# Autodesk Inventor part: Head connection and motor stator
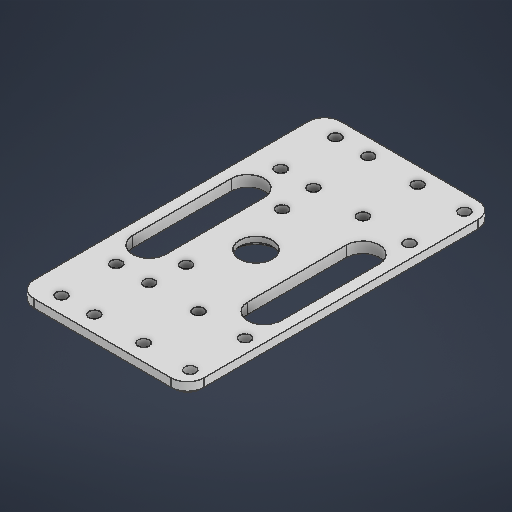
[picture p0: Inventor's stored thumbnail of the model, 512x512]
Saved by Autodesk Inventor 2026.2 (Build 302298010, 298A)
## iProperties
Created: 2026-05
Part Number: Head connection and motor stator
Material: 일반
Document SubType Name: Modeling
Designer: work
Density: 1 g/cm^3
Appearance: 기본값
Author: work
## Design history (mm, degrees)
sketch "스케치1"
  geometry: L1 (-9, 10)-(-26, 10); L2 (-26, 10)-(-26, -10); L3 (-26, -10)-(-9, -10); L4 (-9, -10)-(-9, 10); L5 (-9, 0)-(9, 0); L6 (21, 10)-(9, 10); L7 (9, 10)-(9, -10); L8 (9, -10)-(21, -10); L9 (21, -10)-(21, 10); L10 (-9, -90)-(-9, -70); L11 (-9, -70)-(-26, -70); L12 (-26, -70)-(-26, -90); L13 (-26, -90)-(-9, -90); L14 (-9, -80)-(9, -80); L15 (9, -70)-(9, -90); L16 (9, -90)-(21, -90); L17 (21, -70)-(9, -70); L18 (21, -90)-(21, -70); L19 (0, 0)-(0, -80); L20 (0, -40)-(8, -40); L21 (8, -22.5)-(8, -57.5); L22 (8, -22.5)-(43, -22.5); L23 (-31, 16)-(31, 16); L24 (31, 16)-(31, -96); L25 (31, -96)-(-31, -96); L26 (-31, -96)-(-31, 16); L27 (-31, 16)-(31, -96); L28 (31, 16)-(-31, -96); L29 (-27, -16)-(-15, -16); L30 (-15, -16)-(-15, -64); L31 (-15, -64)-(-27, -64); L32 (-27, -64)-(-27, -16); L33 (-27, -16)-(-15, -64); L34 (-15, -16)-(-27, -64); L35 (-31, -40)-(31, -40); L36 (31, -40)-(-31, -40); L37 (15, -16)-(15, -64); L38 (27, -64)-(27, -16); L39 (27, -16)-(15, -64); L40 (15, -16)-(27, -64); L41 (31, 16)-(-31, -96); L42 (-31, 16)-(31, -96); L43 (27, -16)-(15, -16); L44 (15, -64)-(27, -64); C1 r 2 at (21, 10); C2 r 2 at (9, 10); C3 r 2 at (9, -10); C4 r 2 at (21, -10); C5 r 2 at (-9, 10); C6 r 2 at (-9, -10); C7 r 2 at (-26, -10); C8 r 2 at (-26, 10); C9 r 2 at (-9, -70); C10 r 2 at (-9, -90); C11 r 2 at (-26, -70); C12 r 2 at (-26, -90); C13 r 2 at (9, -90); C14 r 2 at (9, -70); C15 r 2 at (21, -90); C16 r 2 at (21, -70); C17 r 6 at (0, -40); C18 r 2 at (8, -22.5); C19 r 2 at (8, -57.5); 13 further points
  constraints: 88 end point, 20 coincident, 19 centre point, 15 midpoint, 12 parallel, 11 symmetric about line, 10 horizontal, 8 perpendicular, 2 point on line, 1 vertical
  dimensions: "d0" = 20 distance of L3.end L1.start; "d1" = 18 distance of L5.end L5.start; "d2" = 17 distance of L2.end L3.end; "d3" = 12 distance of L8.end L7.end; "d4" = 20 distance of L7.end L6.end; "d5" = 4 diameter of C1; "d6" = 4 diameter of C2; "d7" = 4 diameter of C3; "d8" = 4 diameter of C4; "d9" = 4 diameter of C5; "d10" = 4 diameter of C6; "d11" = 4 diameter of C7; "d12" = 4 diameter of C8; "d13" = 20 distance of L10.start L10.end; "d14" = 18 distance of L14.end L14.start; "d15" = 17 distance of L12.end L10.start; "d16" = 12 distance of L16.end L15.end; "d17" = 20 distance of L15.end L15.start; "d18" = 4 diameter of C16; "d19" = 4 diameter of C14; "d20" = 4 diameter of C13; "d21" = 4 diameter of C15; "d22" = 4 diameter of C9; "d23" = 4 diameter of C10; "d24" = 4 diameter of C12; "d25" = 4 diameter of C11; "d26" = 80 distance of L19.start L19.end; "d27" = 12 diameter of C17; "d28" = 8 distance of L20.start L20.end; "d29" = 35 distance of L21.start L21.end; "d30" = 90 deg angle of L21 L22 (derived); "d31" = 4 diameter of C18; "d32" = 4 diameter of C19; "d33" = 10 distance between parallel lines of L24 L9; "d34" = 6 distance between parallel lines of L23 L6; "d35" = 6 distance from line of point (-17.5, -70) L31; "d36" = 4 distance between parallel lines of L26 L32; "d37" = 10 distance of L35.start point (-21, -40)
extrude "돌출1" new body sketch "스케치1" distance "d38" = 4; taper "d39" = 0 deg
fillet "모깎기1" dims "d40" = 6
chamfer "모따기1" distance "d41" = 2; stored, may be unused: second distance "d42" = 2, angle "d43" = 45 deg
chamfer "모따기2" distance "d44" = 1; stored, may be unused: second distance "d45" = 2, angle "d46" = 45 deg
feature "Ǌ耀ǌ耀ǎ耀ǐ耀ǒ耀ǔ耀ǖ耀ǘ耀" dims "d0" = 20, "d1" = 18, "d2" = 17, "d3" = 12, "d4" = 20, "d5" = 4, "d6" = 4, "d7" = 4, "d8" = 4, "d9" = 4, "d10" = 4, "d11" = 4, "d12" = 4, "d13" = 20, "d14" = 18, "d15" = 17, "d16" = 12, "d17" = 20, "d18" = 4, "d19" = 4, "d20" = 4, "d21" = 4, "d22" = 4, "d23" = 4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
node "솔리드1"
